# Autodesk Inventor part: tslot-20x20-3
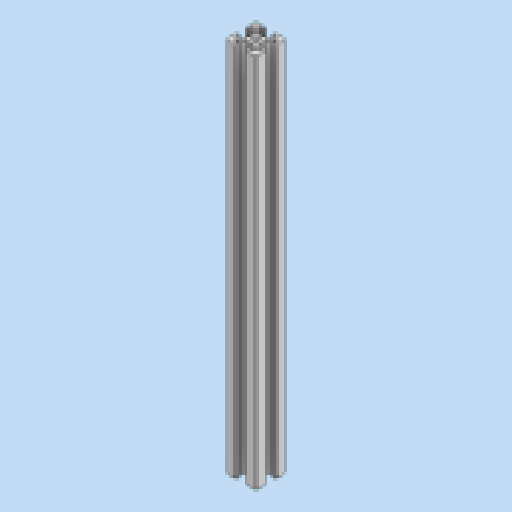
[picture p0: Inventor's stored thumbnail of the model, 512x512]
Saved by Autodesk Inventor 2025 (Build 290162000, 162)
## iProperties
Created: 2025-03
Part Number: tslot-20x20-3
Material: Generico
Document SubType Name: Modeling
Designer: Ryzen5700u
Density: 1 g/cm^3
Appearance: Default
Author: Ryzen5700u
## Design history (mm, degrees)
feature "Base1"
sketch "Schizzo1"
  geometry: L1 (3.761, -16)-(4.7, -16) reference; L2 (3.761, -16)-(0.7, -12.939) reference; L3 (0.7, -12.939)-(0.7, -10.52) reference; L4 (0.4, -10)-(0.7, -10.52) reference; L5 (0.4, -10)-(0.7, -9.48) reference; L6 (0.7, -7.061)-(0.7, -9.48) reference; L7 (3.761, -4)-(0.7, -7.061) reference; L8 (3.761, -4)-(4.7, -4) reference; L9 (4.7, -4)-(4.7, -7) reference; L10 (4.7, -7)-(6.4, -7) reference; L11 (6.7, -6.7)-(6.7, -1) reference; L12 (5.7, 0)-(0, 0) reference; L13 (-0.3, -2)-(-0.3, -0.3) reference; L14 (2.7, -2)-(-0.3, -2) reference; L15 (2.7, -2.939)-(2.7, -2) reference; L16 (2.7, -2.939)-(-0.361, -6) reference; L17 (-0.361, -6)-(-2.78, -6) reference; L18 (-3.3, -6.3)-(-2.78, -6) reference; L19 (-3.3, -6.3)-(-3.82, -6) reference; L20 (-6.239, -6)-(-3.82, -6) reference; L21 (-9.3, -2.939)-(-6.239, -6) reference; L22 (-9.3, -2.939)-(-9.3, -2) reference; L23 (-9.3, -2)-(-6.3, -2) reference; L24 (-6.3, -2)-(-6.3, -0.3) reference; L25 (-12.3, 0)-(-6.6, 0) reference; L26 (-13.3, -6.7)-(-13.3, -1) reference; L27 (-11.3, -7)-(-13, -7) reference; L28 (-11.3, -4)-(-11.3, -7) reference; L29 (-10.361, -4)-(-11.3, -4) reference; L30 (-10.361, -4)-(-7.3, -7.061) reference; L31 (-7.3, -7.061)-(-7.3, -9.48) reference; L32 (-7, -10)-(-7.3, -9.48) reference; L33 (-7, -10)-(-7.3, -10.52) reference; L34 (-7.3, -12.939)-(-7.3, -10.52) reference; L35 (-10.361, -16)-(-7.3, -12.939) reference; L36 (-10.361, -16)-(-11.3, -16) reference; L37 (-11.3, -16)-(-11.3, -13) reference; L38 (-11.3, -13)-(-13, -13) reference; L39 (-13.3, -13.3)-(-13.3, -19) reference; L40 (-12.3, -20)-(-6.6, -20) reference; L41 (-6.3, -18)-(-6.3, -19.7) reference; L42 (-9.3, -18)-(-6.3, -18) reference; L43 (-9.3, -17.061)-(-9.3, -18) reference; L44 (-9.3, -17.061)-(-6.239, -14) reference; L45 (-6.239, -14)-(-3.82, -14) reference; L46 (-3.3, -13.7)-(-3.82, -14) reference; L47 (-3.3, -13.7)-(-2.78, -14) reference; L48 (-0.361, -14)-(-2.78, -14) reference; L49 (2.7, -17.061)-(-0.361, -14) reference; L50 (2.7, -17.061)-(2.7, -18) reference; L51 (2.7, -18)-(-0.3, -18) reference; L52 (-0.3, -18)-(-0.3, -19.7) reference; L53 (5.7, -20)-(0, -20) reference; L54 (6.7, -13.3)-(6.7, -19) reference; L55 (4.7, -13)-(6.4, -13) reference; L56 (4.7, -16)-(4.7, -13) reference; C1 r 2.1 at (-3.3, -10) reference; A1 r 0.3 centre (6.4, -6.7) between (6.4, -7) and (6.7, -6.7) reference; A2 r 1 centre (5.7, -1) between (6.7, -1) and (5.7, 0) reference; A3 r 0.3 centre (0, -0.3) between (0, 0) and (-0.3, -0.3) reference; A4 r 0.3 centre (-6.6, -0.3) between (-6.3, -0.3) and (-6.6, 0) reference; A5 r 1 centre (-12.3, -1) between (-12.3, 0) and (-13.3, -1) reference; A6 r 0.3 centre (-13, -6.7) between (-13.3, -6.7) and (-13, -7) reference; A7 r 0.3 centre (-13, -13.3) between (-13, -13) and (-13.3, -13.3) reference; A8 r 1 centre (-12.3, -19) between (-13.3, -19) and (-12.3, -20) reference; A9 r 0.3 centre (-6.6, -19.7) between (-6.6, -20) and (-6.3, -19.7) reference; A10 r 0.3 centre (0, -19.7) between (-0.3, -19.7) and (0, -20) reference; A11 r 1 centre (5.7, -19) between (5.7, -20) and (6.7, -19) reference; A12 r 0.3 centre (6.4, -13.3) between (6.7, -13.3) and (6.4, -13) reference; 1 further point
extrude "Estrusione1" join sketch "Schizzo1" distance "d0" = 240; taper "d1" = 0 deg
node "Solido1"
node "Linea chiusa proiettata1"
